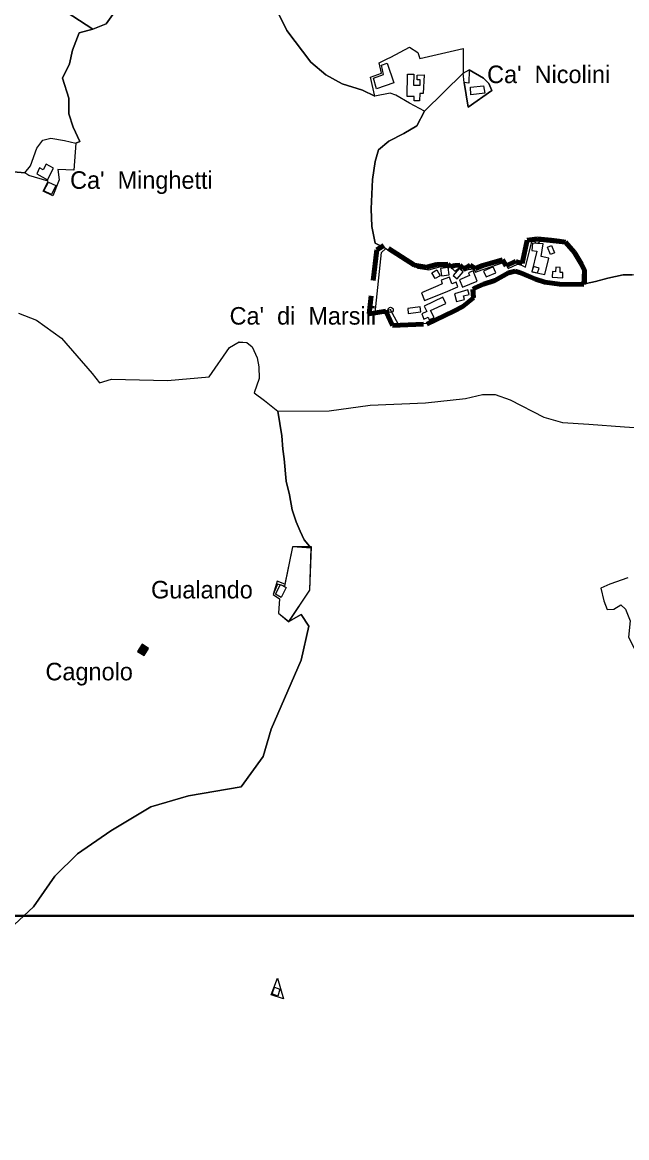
# Model space of a CAD drawing. Extents: x 645880 to 658994, y 884400 to 894744.
# Drawn here: x 655242 to 655828, y 889373 to 890454 of the extents above; entities that cross this region are included whole.
import ezdxf
from ezdxf.enums import TextEntityAlignment as Align

# ---------------------------------------------------------------- set-up
doc = ezdxf.new("R2010")
doc.units = 0
doc.header["$LTSCALE"] = 10
doc.header["$PDMODE"] = 32
doc.header["$PDSIZE"] = 5
doc.linetypes.add('MEDIUM_DASHED', pattern=[4.5, 3, -1.5])
for name, color, linetype, lineweight in [('1', 7, 'Continuous', 25), ('15', 7, 'MEDIUM_DASHED', 100), ('16', 7, 'Continuous', 25), ('18', 7, 'Continuous', 25), ('2', 7, 'Continuous', 25), ('4', 7, 'Continuous', 25), ('63', 7, 'Continuous', 35)]:
    doc.layers.add(name, color=color, linetype=linetype, lineweight=lineweight)
doc.layers.add('60', color=7, linetype='Continuous')

msp = doc.modelspace()

# ---------------------------------------------------------------- hatches: boundary and pattern name
at = {"layer": '4'}
msp.add_hatch(color=256, dxfattribs=at).paths.add_polyline_path([(655358.32, 889851.25), (655353.85, 889844.31), (655360.35, 889840.55), (655364.65, 889847.05)])

# ---------------------------------------------------------------- linework, layer by layer
at = {"layer": '1'}
msp.add_line((655599.3, 890175.45), (655584.18, 890172.68), dxfattribs=at)
for points in [[(655710.66, 890222.06), (655713.3, 890215.42), (655722.41, 890219.66), (655724.92, 890219.34), (655729.93, 890216.73), (655736.03, 890241.82), (655741.4, 890242.47), (655754.66, 890241.17), (655762.55, 890240.19), (655771.15, 890239.21), (655779.08, 890229.33), (655784.41, 890219.66), (655788.71, 890213.8), (655788.71, 890201.09), (655765.05, 890201.41), (655750.72, 890203.37), (655741.76, 890206.3), (655735.67, 890208.91), (655726.35, 890212.82), (655722.05, 890214.12), (655715.6, 890212.49), (655702.34, 890205), (655691.48, 890200.75), (655683.35, 890197.83), (655680.84, 890196.53), (655680.9, 890187.62), (655670.86, 890180.46), (655662.62, 890174.91), (655636.46, 890162.2), (655607.05, 890161.15), (655599.3, 890175.45)], [(655584.18, 890172.68), (655590.52, 890231.06), (655594.61, 890235.03), (655626.03, 890215.89), (655636.35, 890214.14), (655647.83, 890217.62), (655656.65, 890217.54), (655661.45, 890213.04), (655665.43, 890215.75), (655668.53, 890215.8), (655670.8, 890213.47), (655674.39, 890214.45), (655679.76, 890215.1), (655681.55, 890212.17), (655687.61, 890214.15), (655710.66, 890222.06)]]:
    msp.add_lwpolyline(points, dxfattribs=at)
for points in [[(655736.74, 890240.04), (655736.25, 890233.14), (655741.03, 890232.53), (655736.25, 890212.45), (655748.82, 890209.75), (655752.79, 890225.67), (655745.22, 890227.29), (655747.13, 890239.4)], [(655751.23, 890236.28), (655755.08, 890237.87), (655758.01, 890230.77), (655754.16, 890229.18)], [(655639.32, 890211.46), (655644.06, 890214.17), (655647.26, 890208.57), (655642.52, 890205.86)], [(655647.51, 890215.55), (655648.55, 890208.45), (655655.95, 890209.53), (655654.91, 890216.63)], [(655660.02, 890208.89), (655663.93, 890205.6), (655669.65, 890212.41), (655665.74, 890215.7)], [(655666.13, 890204.71), (655669.11, 890197.49), (655683.28, 890203.34), (655679.14, 890213.36), (655674.65, 890211.51), (655675.81, 890208.68)], [(655689.26, 890212.95), (655691.84, 890207.39), (655701.2, 890211.51), (655698.62, 890217.07)], [(655736.32, 890212.77), (655741.78, 890211.23), (655743.2, 890215.83), (655737.66, 890217.53)], [(655756.21, 890212.56), (655755.99, 890207.02), (655766.06, 890206.62), (655766.26, 890211.64), (655763.5, 890211.75), (655763.7, 890216.64), (655759.44, 890216.81), (655759.25, 890212.44)], [(655629.35, 890192.01), (655632.11, 890184.42), (655652.44, 890192.75), (655664.45, 890197.67), (655662.73, 890202.4), (655658.5, 890200.86), (655656.25, 890207.03), (655648.29, 890204.13), (655649.23, 890200.68), (655645.15, 890198.79)], [(655631.71, 890179.12), (655634.24, 890173.96), (655629.45, 890171.63), (655631.36, 890166.34), (655635.65, 890168.35), (655636.81, 890165.88), (655641.51, 890168.09), (655638.05, 890174.73), (655652.87, 890181.7), (655650, 890187.73)], [(655661.18, 890191), (655663.04, 890183.66), (655670.78, 890185.67), (655669.86, 890189.1), (655675.45, 890190.44), (655674.2, 890194.91)], [(655615.87, 890176.74), (655616.25, 890172.04), (655628.66, 890173.48), (655628.07, 890178.38)]]:
    msp.add_lwpolyline(points, close=True, dxfattribs=at)
msp.add_point((655599.3, 890175.45), dxfattribs=at)
at = {"layer": '15'}
for points in [[(655748.72, 890202.27), (655763.05, 890200.31), (655786.71, 890199.99), (655787.27, 890213.51), (655784.26, 890219.75), (655777.38, 890230.93), (655768.79, 890241.25), (655762.64, 890242.05), (655754.75, 890243.03), (655741.71, 890244.26), (655731.61, 890242.97), (655726.88, 890220.39), (655723.65, 890221.47), (655720.65, 890222.76)], [(655720.65, 890222.76), (655711.19, 890218.03), (655707.75, 890223.83), (655688.62, 890218.46), (655681.1, 890215.66), (655676.37, 890218.89), (655673.08, 890216.7), (655669.49, 890215.72), (655666.27, 890218.89), (655661.34, 890218.38), (655657.4, 890217.08), (655654.88, 890219.75), (655643.7, 890219.53), (655634.03, 890216.95), (655622.43, 890218.89), (655592.56, 890237.82), (655586.07, 890233.62), (655578.43, 890171.56), (655594.49, 890174.38), (655601.15, 890160.4), (655634.31, 890161.64), (655660.47, 890174.35), (655669.16, 890178.81), (655679.6, 890187.28), (655678.84, 890195.43), (655681.35, 890196.73), (655689.23, 890200.31), (655700.34, 890203.9), (655713.6, 890211.39), (655720.05, 890213.02), (655724.35, 890211.72), (655733.67, 890207.81), (655739.76, 890205.2), (655748.72, 890202.27)]]:
    msp.add_lwpolyline(points, dxfattribs=at)
at = {"layer": '16'}
for points in [[(655310.73, 890447.52), (655323.57, 890452.71), (655336.37, 890470.85), (655349.17, 890503.93), (655352.37, 890526.34), (655360.9, 890548.75), (655366, 890555.06)], [(655583.86, 890382.52), (655572.05, 890388.55), (655552.45, 890394.67), (655536.53, 890403.25), (655521.83, 890415.51), (655498.56, 890446.15), (655476.51, 890491.5), (655456.91, 890530.73), (655445.88, 890533.18), (655433.63, 890534.4), (655423.83, 890542.98), (655414.58, 890564.19)], [(655476.51, 890491.5), (655498.56, 890446.15), (655521.83, 890415.51), (655536.53, 890403.25), (655552.45, 890394.67), (655572.05, 890388.55), (655583.86, 890382.52), (655579.64, 890401.22), (655590.49, 890404.84), (655588.08, 890415.1), (655595.92, 890418.72), (655599.46, 890420.58), (655617.54, 890430.08), (655625.54, 890425.08), (655627.54, 890419.08), (655669.69, 890428.89), (655669.51, 890405.08), (655675.49, 890408.13), (655689.4, 890400.01), (655694.4, 890395.01), (655697.39, 890388.01), (655674.41, 890372), (655670.57, 890396.01), (655669.51, 890405.08), (655632.09, 890368.03)], [(655152.23, 890456.28), (655163.35, 890470.47), (655173.64, 890479.1), (655185.87, 890460.18), (655194.49, 890472.42), (655203.39, 890481.88), (655229.25, 890480.49), (655260.12, 890474.93), (655284.74, 890464.35), (655310.73, 890447.52)], [(655336.37, 890470.85), (655323.57, 890452.71), (655310.73, 890447.52), (655297.48, 890443.97), (655290.98, 890427.34), (655287.93, 890413.99), (655281.08, 890400.19), (655287.37, 890380.6), (655287.44, 890365.64), (655291.63, 890352.64), (655298.01, 890338.65), (655294.14, 890337.23), (655292.36, 890310.97), (655276.87, 890311.47), (655277.87, 890301.47), (655271.88, 890285.97), (655262.52, 890290.57), (655267.33, 890300.21), (655248.74, 890305.75), (655244.71, 890308.44), (655226.17, 890309.83)], [(655580.59, 890273.45), (655581.85, 890301.77), (655584.37, 890319.39), (655587.51, 890330.71), (655597.57, 890338.9), (655612.04, 890346.45), (655624.62, 890354), (655632.09, 890368.03), (655617.62, 890375.88), (655604.36, 890383.72), (655598.93, 890385.53), (655583.86, 890382.52)], [(655632.09, 890368.03), (655624.62, 890354), (655612.04, 890346.45), (655597.57, 890338.9), (655587.51, 890330.71), (655584.37, 890319.39), (655581.85, 890301.77), (655580.59, 890273.45)], [(655594.61, 890235.03), (655584.37, 890240.09), (655581.22, 890256.45), (655580.59, 890273.45)], [(655580.59, 890273.45), (655581.22, 890256.45), (655584.37, 890240.09), (655594.61, 890235.03), (655626.03, 890215.89), (655636.35, 890214.14), (655647.83, 890217.62), (655656.65, 890217.54), (655661.45, 890213.04), (655665.43, 890215.75), (655668.53, 890215.8), (655670.8, 890213.47), (655674.39, 890214.45), (655679.76, 890215.1), (655681.55, 890212.17), (655687.61, 890214.15), (655710.66, 890222.06)], [(655710.66, 890222.06), (655713.3, 890215.42), (655722.41, 890219.66), (655724.92, 890219.34), (655729.93, 890216.73), (655736.03, 890241.82), (655741.4, 890242.47)], [(655741.4, 890242.47), (655762.55, 890240.19), (655771.15, 890239.21), (655779.08, 890229.33), (655784.41, 890219.66), (655788.71, 890213.8), (655788.71, 890201.09)], [(655833.48, 890209.28), (655824.54, 890209.28), (655809.8, 890206.15), (655797.74, 890203.02), (655788.71, 890201.09), (655765.05, 890201.41), (655750.72, 890203.37), (655741.76, 890206.3), (655735.67, 890208.91), (655726.35, 890212.82), (655722.05, 890214.12), (655715.6, 890212.49), (655702.34, 890205), (655691.48, 890200.75), (655683.35, 890197.83), (655680.84, 890196.53), (655680.9, 890187.62), (655670.86, 890180.46), (655662.62, 890174.91), (655636.46, 890162.2), (655607.05, 890161.15), (655599.3, 890175.45), (655584.18, 890172.68), (655590.52, 890231.06), (655594.61, 890235.03)], [(655788.71, 890201.09), (655797.74, 890203.02), (655809.8, 890206.15), (655824.54, 890209.28), (655833.48, 890209.28), (655843.75, 890209.73), (655849.31, 890210.78), (655853.15, 890213.11), (655857.19, 890221.07), (655858.39, 890221.77), (655860.29, 890221.17), (655864.49, 890219.17), (655870.99, 890209.17), (655872.49, 890201.37), (655871.69, 890193.57)], [(655238.48, 890172.26), (655256.14, 890165.49), (655280.16, 890147.89), (655309.88, 890113.68), (655317.24, 890104.73), (655328.81, 890108.42), (655382.98, 890107.1), (655423.49, 890110.54), (655443.22, 890138.95), (655452.12, 890144.28)], [(655452.12, 890144.28), (655459.76, 890143.7), (655465.06, 890139.58), (655469.77, 890128.97)], [(655469.77, 890128.97), (655471.67, 890120.17), (655471.96, 890108.98), (655467.12, 890095.11), (655477.1, 890087.65), (655490.07, 890077.44), (655539.7, 890077.52), (655579.35, 890083.18), (655632.99, 890085.44), (655671.91, 890089.41), (655688.23, 890093.37), (655700.48, 890093.37), (655715.05, 890088.28), (655747.7, 890071.31), (655765.78, 890066.22), (655791.43, 890064.52), (655826.07, 890062.18), (655845.12, 890060.86)], [(655829.16, 889915.85), (655811.93, 889909.51), (655803.01, 889905.73), (655805.93, 889893.29), (655809.21, 889885.01)], [(655809.21, 889885.01), (655815.56, 889885.31), (655822.41, 889889.4), (655826.92, 889885.37), (655831.58, 889874.05), (655829.76, 889858.09), (655835.08, 889848.03), (655843.06, 889842.67), (655868.23, 889840.89), (655887.47, 889841.46), (655899.13, 889846.55), (655906.13, 889850.51), (655932.95, 889843.72), (655940.56, 889851.1)]]:
    msp.add_lwpolyline(points, dxfattribs=at)
msp.add_point((655741.4, 890242.47), dxfattribs=at)
at = {"layer": '18'}
for points in [[(655226.17, 890309.83), (655244.71, 890308.44), (655250.36, 890315.15), (655256.33, 890332.35), (655262.12, 890339.95), (655270.08, 890341.94), (655283.11, 890339.59), (655294.14, 890337.23), (655298.01, 890338.65), (655291.63, 890352.64), (655287.44, 890365.64), (655287.37, 890380.6), (655281.08, 890400.19), (655287.93, 890413.99), (655290.98, 890427.34), (655297.48, 890443.97), (655310.73, 890447.52), (655284.74, 890464.35), (655260.12, 890474.93), (655229.25, 890480.49)], [(655238.48, 890172.26), (655256.14, 890165.49), (655280.16, 890147.89), (655309.88, 890113.68), (655317.24, 890104.73), (655328.81, 890108.42), (655382.98, 890107.1), (655423.49, 890110.54), (655443.22, 890138.95), (655452.42, 890144.47)], [(655452.42, 890144.47), (655459.76, 890143.7), (655465.06, 890139.58), (655469.77, 890128.97)], [(655469.77, 890128.97), (655471.67, 890120.17), (655471.96, 890108.98), (655467.12, 890095.11), (655477.1, 890087.65), (655490.07, 890077.44)], [(655579.35, 890083.18), (655632.99, 890085.44), (655671.91, 890089.41), (655688.23, 890093.37), (655700.48, 890093.37), (655715.05, 890088.28), (655747.7, 890071.31), (655765.78, 890066.22), (655791.43, 890064.52), (655826.07, 890062.18), (655845.12, 890060.86)], [(655522.14, 889944.49), (655515.6, 889952.67), (655511.51, 889960.85), (655507.84, 889969.85), (655503.75, 889981.71), (655501.3, 889996.02), (655498.03, 890009.52), (655495.98, 890031.19), (655494.76, 890040.6), (655493.94, 890053.28), (655490.07, 890077.44), (655539.7, 890077.52), (655579.35, 890083.18)], [(655490.07, 890077.44), (655493.94, 890053.28), (655494.76, 890040.6), (655495.98, 890031.19), (655498.03, 890009.52), (655501.3, 889996.02), (655503.75, 889981.71), (655507.84, 889969.85), (655511.51, 889960.85), (655515.6, 889952.67), (655522.14, 889944.49), (655504.08, 889945.84), (655496.54, 889907.5), (655489.54, 889909.5), (655485.54, 889899.49), (655491.54, 889895.49), (655490.54, 889881.49), (655500.71, 889873.24)], [(655500.71, 889873.24), (655520.95, 889903.63), (655522.14, 889944.49)], [(655829.16, 889915.85), (655811.93, 889909.51), (655803.01, 889905.73), (655805.93, 889893.29), (655809.21, 889885.01), (655815.56, 889885.31), (655822.41, 889889.4), (655826.92, 889885.37), (655831.58, 889874.05)], [(655229.72, 889575.13), (655253.2, 889596.67), (655273.75, 889626.54), (655295.77, 889648.08), (655328.06, 889670.61), (655366.72, 889693.61), (655403.42, 889704.39), (655454.3, 889713.2), (655475.83, 889742.58), (655483.66, 889769.02), (655512.63, 889835.97), (655519.86, 889868.9), (655512.52, 889880.16), (655500.71, 889873.24)], [(655500.71, 889873.24), (655512.52, 889880.16), (655519.86, 889868.9), (655512.63, 889835.97), (655483.66, 889769.02), (655475.83, 889742.58), (655454.3, 889713.2), (655403.42, 889704.39), (655366.72, 889693.61), (655328.06, 889670.61), (655295.77, 889648.08), (655273.75, 889626.54), (655253.2, 889596.67), (655229.72, 889575.13)]]:
    msp.add_lwpolyline(points, dxfattribs=at)
at = {"layer": '2'}
for points in [[(655590.32, 890412.65), (655595.96, 890414.64), (655602.26, 890395.53), (655585.63, 890389.89), (655582.8, 890400.07), (655592.31, 890403.69)], [(655615.72, 890404.02), (655621.84, 890403.85), (655621.6, 890393.15), (655627.81, 890393.23), (655628.08, 890398.39), (655624.99, 890398.54), (655624.94, 890403.12), (655631.66, 890403.22), (655630.96, 890385.26), (655627.48, 890385.26), (655627.31, 890378.13), (655622.17, 890378.13), (655622.15, 890382.29), (655615.37, 890382.44)], [(655676.57, 890391.34), (655689.47, 890392.79), (655690.47, 890385.71), (655677.16, 890383.91)], [(655259.05, 890313.16), (655256.33, 890307.19), (655266.83, 890301.57), (655272.62, 890312.98), (655265.38, 890316.78), (655262.49, 890311.17)], [(655267.67, 890299.15), (655274.66, 890296.03), (655270.43, 890287.31), (655263.26, 890290.82)]]:
    msp.add_lwpolyline(points, close=True, dxfattribs=at)
for points in [[(655256.33, 890332.35), (655262.12, 890339.95), (655270.08, 890341.94), (655283.11, 890339.59), (655294.14, 890337.23), (655292.36, 890310.97), (655276.87, 890311.47), (655277.87, 890301.47), (655271.88, 890285.97), (655262.52, 890290.57), (655267.33, 890300.21)], [(655267.33, 890300.21), (655248.74, 890305.75), (655244.71, 890308.44), (655250.36, 890315.15), (655256.33, 890332.35)]]:
    msp.add_lwpolyline(points, dxfattribs=at)
at = {"layer": '4'}
for points in [[(655617.62, 890375.88), (655604.36, 890383.72), (655598.93, 890385.53), (655583.86, 890382.52), (655579.64, 890401.22), (655590.49, 890404.84), (655588.08, 890415.1), (655595.92, 890418.72), (655599.46, 890420.58), (655617.54, 890430.08), (655625.54, 890425.08), (655627.54, 890419.08), (655669.69, 890428.89), (655669.51, 890405.08), (655632.09, 890368.03)], [(655670.57, 890396.01), (655674.41, 890372), (655697.39, 890388.01), (655694.4, 890395.01), (655689.4, 890400.01), (655675.49, 890408.13), (655675.17, 890395.35)], [(655487.74, 889899.77), (655492.6, 889909.26), (655498.02, 889906.27), (655493.04, 889896.75)], [(655358.32, 889851.25), (655353.85, 889844.31), (655360.35, 889840.55), (655364.65, 889847.05)], [(655356.36, 889845), (655359.18, 889848.94), (655362.94, 889846.11), (655360.2, 889842.52)], [(655483.5, 889511.51), (655489.5, 889527.51), (655495.5, 889507.5)], [(655486.88, 889518.81), (655491.79, 889516.87), (655489.85, 889510.24), (655484.48, 889512.41)]]:
    msp.add_lwpolyline(points, close=True, dxfattribs=at)
for points in [[(655496.69, 889909.73), (655489.45, 889912.54), (655485.48, 889899.51), (655491.48, 889895.51), (655490.51, 889881.46), (655500.68, 889873.21), (655520.92, 889903.6), (655522.6, 889945.81)], [(655522.6, 889945.81), (655504.05, 889945.81), (655496.69, 889909.73)]]:
    msp.add_lwpolyline(points, dxfattribs=at)
at = {"layer": '63', "lineweight": 40}
msp.add_lwpolyline([(656397.82, 884399.72), (650080.32, 884399.72), (650080.32, 889588.16), (656397.82, 889588.16)], close=True, dxfattribs=at)

# ---------------------------------------------------------------- texts
at = {"layer": '60'}
for s, p in [("Ca'  Nicolini", (655752.48, 890395.29)), ("Ca'  Minghetti", (655357.73, 890292.82)), ("Ca'  di  Marsili", (655514.21, 890161.19)), ('Gualando', (655416.38, 889895.73)), ('Cagnolo', (655307.08, 889816.36))]:
    msp.add_text(s, height=17, dxfattribs=at).set_placement(p, align=Align.CENTER)

doc.saveas('drawing.dxf')
